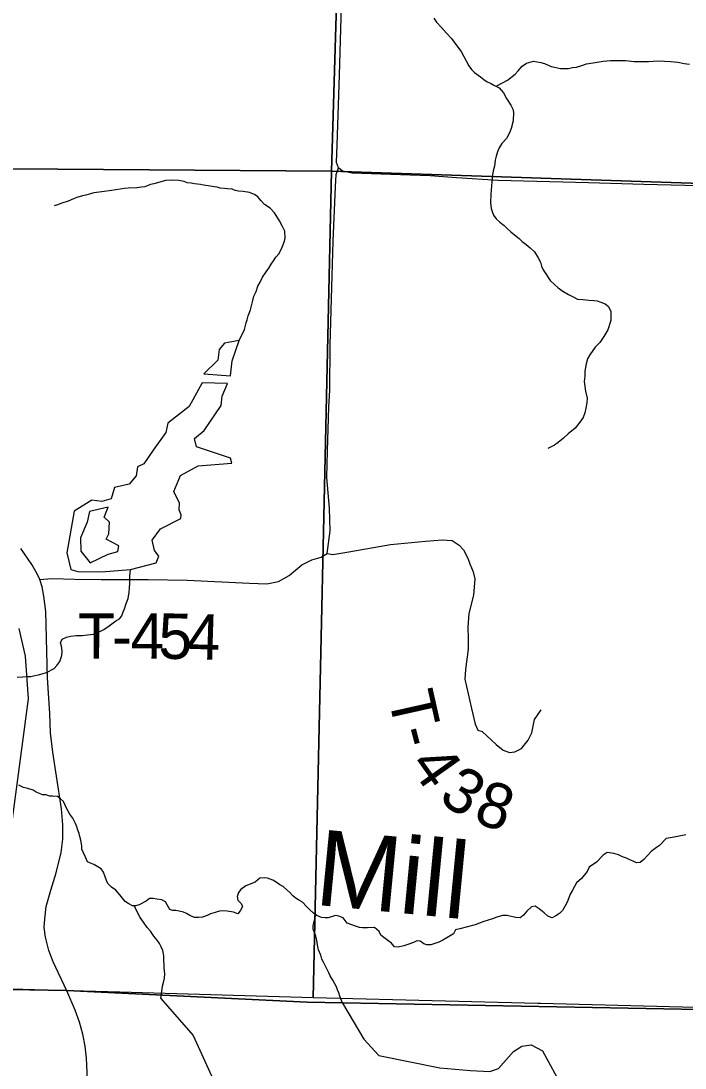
# Model space of a CAD drawing. Extents: x 0 to 34, y 0 to 22.
# Drawn here: x 5.636 to 6.467, y 16.238 to 17.548 of the extents above; entities that cross this region are included whole.
import ezdxf

# ---------------------------------------------------------------- set-up
doc = ezdxf.new("R2010")
doc.units = 0
for name, color, linetype in [('GM_X_Corporation', 7, 'Continuous'), ('GM_X_County_Road', 7, 'Continuous'), ('GM_X_Minor_Lake', 7, 'Continuous'), ('GM_X_Minor_River', 7, 'Continuous'), ('GM_X_Minor_River_Text', 7, 'Continuous'), ('GM_X_Rail_Line', 7, 'Continuous'), ('GM_X_State_Route', 7, 'Continuous'), ('GM_X_Township_Road', 7, 'Continuous'), ('GM_X_Township_Road_Text', 7, 'Continuous')]:
    doc.layers.add(name, color=color, linetype=linetype)

msp = doc.modelspace()

# ---------------------------------------------------------------- linework, layer by layer
at = {"layer": 'GM_X_Corporation'}
for points in [[(4.9914, 16.3477), (5.6931, 16.3352), (5.9938, 16.3204), (6.9309, 16.303), (7.0302, 16.2995), (7.0491, 16.2993), (8.0233, 16.275), (8.785, 16.2515), (8.9, 16.2485), (8.9, 20.9), (2.1, 20.9)], [(4.9914, 16.3477), (5.6931, 16.3352), (5.9938, 16.3204), (6.9309, 16.303), (7.0302, 16.2995), (7.0306, 16.367), (7.0337, 16.3927), (7.0334, 16.423), (7.0339, 16.4517), (7.0342, 16.5147), (7.0361, 16.5712), (7.0442, 17.0463), (7.0729, 18.3402), (7.0876, 19.4092), (7.1008, 19.81), (7.1249, 20.7061), (7.1302, 20.9), (2.2795, 20.9)], [(8.9, 14.5591), (8.9, 16.2485), (8.785, 16.2515), (8.0233, 16.275), (7.0491, 16.2993), (7.0302, 16.2995), (6.9309, 16.303), (5.9938, 16.3204), (5.6931, 16.3352), (4.9914, 16.3477), (4.4958, 16.358), (3.9899, 16.3631), (3.7537, 16.3728), (3.6165, 16.3686), (3.0057, 16.3809), (2.7707, 16.392), (2.3623, 16.41), (2.2605, 16.4147), (2.1155, 16.4201), (2.1, 15.9517)], [(8.9, 14.1), (8.9, 16.2485), (8.785, 16.2515), (8.0233, 16.275), (7.0491, 16.2993), (7.0302, 16.2995), (6.9309, 16.303), (5.9938, 16.3204), (5.6931, 16.3352), (4.9914, 16.3477)]]:
    msp.add_lwpolyline(points, dxfattribs=at)
for points in [[(5.0167, 18.3983), (6.0547, 18.3798), (6.0244, 17.3604), (4.9971, 17.3675)], [(7.0725, 18.3472), (7.0493, 17.3262), (6.0244, 17.3604), (6.0547, 18.3798)], [(4.9971, 17.3675), (6.0244, 17.3604), (6.0014, 16.3259), (5.7595, 16.3331), (5.486, 16.3408), (5.2494, 16.3478), (4.9974, 16.3535)], [(6.0244, 17.3604), (7.0493, 17.3262), (7.0242, 16.3016), (6.7708, 16.3075), (6.5283, 16.3127), (6.2859, 16.3188), (6.2825, 16.3189), (6.018, 16.3254), (6.0014, 16.3259)]]:
    msp.add_lwpolyline(points, close=True, dxfattribs=at)
at = {"layer": 'GM_X_County_Road'}
for points in [[(6.033, 17.3642), (6.0307, 17.371), (6.0314, 17.3933), (6.0345, 17.4804), (6.0385, 17.6249), (6.0421, 17.7526), (6.0425, 17.7762), (6.0418, 17.8051), (6.0431, 17.8132), (6.0462, 17.8213), (6.0524, 17.8366)], [(6.5006, 17.3416), (6.4153, 17.3437), (6.3459, 17.3454), (6.2327, 17.3485), (6.1808, 17.3518), (6.1479, 17.3543), (6.1226, 17.3553), (6.0502, 17.3578), (6.0383, 17.3601), (6.033, 17.3642)]]:
    msp.add_lwpolyline(points, dxfattribs=at)
at = {"layer": 'GM_X_Minor_Lake'}
for points in [[(5.909, 17.1483), (5.8904, 17.1452), (5.884, 17.1369), (5.8822, 17.1236), (5.8648, 17.1065), (5.8981, 17.1043)], [(5.8981, 17.1043), (5.9, 17.1229), (5.909, 17.1483)], [(5.8626, 17.0955), (5.8463, 17.0659), (5.8195, 17.045), (5.8173, 17.0332), (5.8014, 17.0112), (5.7897, 16.9941), (5.7818, 16.9903), (5.7799, 16.9789), (5.7712, 16.9686), (5.7527, 16.9644), (5.7489, 16.9504), (5.7372, 16.9469), (5.7247, 16.9488), (5.7024, 16.9347), (5.6934, 16.8827), (5.6984, 16.8619), (5.7071, 16.8592), (5.7367, 16.8589), (5.7731, 16.862)], [(5.7731, 16.862), (5.8052, 16.8704), (5.8082, 16.8784), (5.8029, 16.8856), (5.7999, 16.8985), (5.8104, 16.9129), (5.8358, 16.9255), (5.8361, 16.9301), (5.8338, 16.9365), (5.8342, 16.9448), (5.8273, 16.9596), (5.8356, 16.9794), (5.8576, 16.9915), (5.8996, 16.9947), (5.8981, 17.0011), (5.8556, 17.0154), (5.8529, 17.0257), (5.865, 17.0356), (5.8865, 17.0671), (5.8876, 17.0789), (5.8944, 17.0944), (5.8626, 17.0955)], [(5.7448, 16.9397), (5.7217, 16.9344), (5.7187, 16.9211), (5.7104, 16.9013), (5.7108, 16.885), (5.7226, 16.8703)], [(5.7226, 16.8703), (5.745, 16.8809), (5.7571, 16.8844), (5.7582, 16.8916), (5.7423, 16.8999), (5.746, 16.9063), (5.7467, 16.9211), (5.7399, 16.9272), (5.7448, 16.9397)]]:
    msp.add_lwpolyline(points, dxfattribs=at)
at = {"layer": 'GM_X_Minor_River'}
for points in [[(6.1526, 17.5516), (6.1556, 17.5467), (6.1621, 17.5398), (6.1682, 17.533), (6.1746, 17.5262), (6.1811, 17.5171), (6.1864, 17.5099), (6.1899, 17.5035), (6.196, 17.4921), (6.1994, 17.4872), (6.2032, 17.4838), (6.2108, 17.4781), (6.215, 17.4747), (6.2191, 17.4721), (6.2233, 17.4702), (6.2275, 17.4679), (6.2343, 17.4645), (6.2397, 17.4581), (6.2435, 17.4513), (6.2488, 17.4429), (6.2511, 17.4376), (6.2522, 17.4339), (6.2515, 17.4232), (6.2493, 17.4137), (6.247, 17.4081), (6.2432, 17.4012), (6.2376, 17.3948)], [(6.2302, 17.4666), (6.2445, 17.474), (6.254, 17.4816), (6.2581, 17.4858), (6.2627, 17.4915), (6.2683, 17.4953), (6.277, 17.498), (6.2861, 17.4961), (6.2907, 17.495), (6.299, 17.4912), (6.3032, 17.4901), (6.3108, 17.4886), (6.321, 17.4886), (6.326, 17.4898), (6.3309, 17.4901), (6.3377, 17.4924), (6.3434, 17.4943), (6.3517, 17.4959), (6.3642, 17.4978), (6.3733, 17.4986), (6.3922, 17.4986), (6.4032, 17.4975), (6.421, 17.4975), (6.4267, 17.4979), (6.4366, 17.4983), (6.4411, 17.498), (6.4483, 17.4972), (6.4578, 17.4965), (6.4654, 17.495), (6.4722, 17.4942)], [(6.2376, 17.3948), (6.2342, 17.3894), (6.2319, 17.3845), (6.2304, 17.3788), (6.2293, 17.3739), (6.2282, 17.3663), (6.2267, 17.3606), (6.2252, 17.3526), (6.2248, 17.3473), (6.2245, 17.3413), (6.2237, 17.3314), (6.2234, 17.3204), (6.2242, 17.3136), (6.2253, 17.3098), (6.2272, 17.3052), (6.2303, 17.3007), (6.2348, 17.2962), (6.2402, 17.2924), (6.2443, 17.2886), (6.2489, 17.2844), (6.2534, 17.2806), (6.2591, 17.2761), (6.2629, 17.2723), (6.2679, 17.2685), (6.2728, 17.2644), (6.2785, 17.2591), (6.2831, 17.2519), (6.2858, 17.2462), (6.2873, 17.2413), (6.2892, 17.2367), (6.2915, 17.2329), (6.298, 17.2235), (6.3033, 17.2186), (6.3078, 17.2144), (6.3139, 17.2102), (6.3207, 17.2061), (6.3268, 17.2031), (6.3321, 17.2), (6.339, 17.1997), (6.3465, 17.1989), (6.3526, 17.1982), (6.3568, 17.1978), (6.3613, 17.1963), (6.3666, 17.1944), (6.3708, 17.191), (6.3739, 17.1846), (6.3739, 17.1732), (6.3701, 17.1618), (6.3649, 17.1534), (6.36, 17.1458), (6.3543, 17.1401), (6.3475, 17.1303), (6.3445, 17.1253), (6.343, 17.1193), (6.3415, 17.1098), (6.3411, 17.1037), (6.3404, 17.0969), (6.3423, 17.0851), (6.3442, 17.0764), (6.3439, 17.0703), (6.3424, 17.0635), (6.3413, 17.0578), (6.3394, 17.0521), (6.3352, 17.046), (6.3292, 17.0388), (6.3205, 17.0316), (6.3145, 17.0263), (6.308, 17.0206), (6.3035, 17.0175), (6.2952, 17.0133)], [(5.909, 17.1483), (5.9154, 17.162), (5.9177, 17.1703), (5.9188, 17.1741), (5.9203, 17.1791), (5.9229, 17.1867), (5.9248, 17.1935), (5.9259, 17.1984), (5.9274, 17.2037), (5.93, 17.2098), (5.9323, 17.2163), (5.9353, 17.2212), (5.938, 17.2276), (5.9425, 17.2341), (5.9459, 17.2387), (5.9489, 17.244), (5.9519, 17.2482), (5.9549, 17.2527), (5.9591, 17.2573), (5.9628, 17.2652), (5.9655, 17.2725), (5.9662, 17.277), (5.9658, 17.285), (5.9628, 17.2918), (5.9593, 17.2982), (5.9559, 17.3035), (5.9529, 17.3081), (5.9475, 17.3138), (5.9407, 17.3187), (5.9365, 17.3232), (5.9323, 17.3281), (5.9282, 17.3308), (5.9217, 17.3334), (5.9138, 17.3349), (5.9081, 17.3353), (5.9039, 17.336), (5.9001, 17.3375), (5.8944, 17.3379), (5.8903, 17.3387), (5.8849, 17.339), (5.8812, 17.3402), (5.8774, 17.3405), (5.8702, 17.342), (5.8641, 17.3428), (5.8603, 17.3435), (5.8531, 17.3443), (5.8489, 17.345), (5.844, 17.3458), (5.8402, 17.3473), (5.8334, 17.3484), (5.8239, 17.3488), (5.8167, 17.3484), (5.8125, 17.3472), (5.8019, 17.3442), (5.7978, 17.3434), (5.791, 17.3407), (5.7868, 17.3403), (5.7807, 17.3392), (5.7698, 17.3388), (5.7652, 17.3384), (5.7546, 17.3369), (5.7493, 17.3361), (5.7372, 17.3342), (5.7269, 17.333), (5.7228, 17.3319), (5.7171, 17.33), (5.7129, 17.3292), (5.7057, 17.3273), (5.7016, 17.3257), (5.6951, 17.3227), (5.6868, 17.32), (5.6815, 17.3181), (5.6774, 17.317)], [(5.6313, 16.727), (5.6378, 16.7274), (5.6431, 16.7278), (5.6484, 16.7278), (5.6533, 16.7294), (5.6579, 16.7301), (5.6677, 16.7328), (5.6775, 16.7381), (5.6806, 16.7419), (5.6847, 16.7469), (5.687, 16.7541), (5.6873, 16.7598), (5.6866, 16.7659), (5.6854, 16.77), (5.6873, 16.7746), (5.693, 16.7773), (5.6979, 16.7784), (5.7051, 16.7792), (5.7123, 16.7792), (5.7191, 16.78), (5.7267, 16.7811), (5.7327, 16.7834), (5.7395, 16.7868), (5.7464, 16.7914), (5.7547, 16.7975), (5.7592, 16.8002), (5.7619, 16.804), (5.7637, 16.8089), (5.7652, 16.8127), (5.7675, 16.8195), (5.7698, 16.8256), (5.7712, 16.8336), (5.7716, 16.8385), (5.772, 16.8446), (5.7719, 16.8533), (5.7731, 16.862), (5.7731, 16.862)], [(5.7321, 16.4898), (5.7271, 16.4928), (5.723, 16.4943), (5.7192, 16.4962), (5.7165, 16.5019), (5.7135, 16.5083), (5.7119, 16.5121), (5.7119, 16.5163), (5.7108, 16.5231), (5.7096, 16.5277), (5.7085, 16.5314), (5.7069, 16.5356), (5.7058, 16.5398), (5.7039, 16.5443), (5.7008, 16.5508), (5.697, 16.5557), (5.6951, 16.5595), (5.6928, 16.5633), (5.6913, 16.5671), (5.689, 16.5716), (5.6852, 16.575), (5.6814, 16.5777), (5.6754, 16.5784), (5.6716, 16.5784), (5.6674, 16.5799), (5.6628, 16.5799), (5.6591, 16.5818), (5.6549, 16.5833), (5.6511, 16.5856), (5.6443, 16.5878), (5.6389, 16.589), (5.6333, 16.592)], [(6.4675, 16.53), (6.4614, 16.5285), (6.4531, 16.5269), (6.4432, 16.5254), (6.4349, 16.5166), (6.4308, 16.514), (6.4243, 16.509), (6.4153, 16.4991), (6.4107, 16.4953), (6.4058, 16.495), (6.4016, 16.4968), (6.3978, 16.4987), (6.3933, 16.5006), (6.3884, 16.5025), (6.3834, 16.5048), (6.3774, 16.5067), (6.3694, 16.5078), (6.3641, 16.5044), (6.3558, 16.4956), (6.3467, 16.4895), (6.3441, 16.4842), (6.3373, 16.4751), (6.3309, 16.4698), (6.3282, 16.4652), (6.3256, 16.4599), (6.3229, 16.4557), (6.3214, 16.4511), (6.3192, 16.4458), (6.3169, 16.4409), (6.3135, 16.4352), (6.3097, 16.4314), (6.3052, 16.4284), (6.3003, 16.4261), (6.295, 16.428), (6.2904, 16.4325), (6.284, 16.4374), (6.279, 16.4408), (6.2745, 16.4397), (6.2688, 16.4343), (6.2647, 16.4294), (6.2605, 16.426), (6.2548, 16.4263), (6.2491, 16.4279), (6.2442, 16.429), (6.2381, 16.429), (6.2313, 16.4271), (6.2256, 16.4248), (6.2203, 16.4232), (6.215, 16.4213), (6.2041, 16.4175)], [(6.2041, 16.4175), (6.1851, 16.4122), (6.1794, 16.411), (6.1768, 16.4061), (6.1685, 16.4011), (6.1636, 16.3981), (6.1586, 16.3958), (6.1537, 16.3939), (6.1488, 16.3924), (6.1435, 16.3924), (6.1397, 16.3935), (6.1351, 16.3969), (6.131, 16.3973), (6.1268, 16.3954), (6.1211, 16.3931), (6.1147, 16.3912), (6.1079, 16.3892), (6.1033, 16.39), (6.0995, 16.3942), (6.095, 16.3976), (6.09, 16.4013), (6.0859, 16.4044), (6.084, 16.4089), (6.0783, 16.4138), (6.0695, 16.4134), (6.0631, 16.4134), (6.0593, 16.4138), (6.0544, 16.4157), (6.0487, 16.4176), (6.0438, 16.4195), (6.0388, 16.4259), (6.0335, 16.4282), (6.0293, 16.4289), (6.0202, 16.4262), (6.0165, 16.4262), (6.0119, 16.4266), (6.0062, 16.4289), (6.002, 16.4319), (5.9967, 16.4364), (5.9929, 16.4402), (5.988, 16.4455), (5.9842, 16.4478), (5.98, 16.4504), (5.9758, 16.4535), (5.9724, 16.4576), (5.9686, 16.461), (5.9637, 16.4652), (5.9599, 16.4675), (5.9553, 16.4709), (5.9508, 16.4731), (5.9443, 16.4758), (5.9401, 16.4762), (5.9348, 16.4758), (5.9288, 16.4708), (5.9174, 16.4662), (5.911, 16.4617), (5.908, 16.4579), (5.9065, 16.4529), (5.9073, 16.448), (5.9114, 16.4442), (5.913, 16.4404), (5.9103, 16.4347), (5.9073, 16.4309), (5.9016, 16.4332), (5.894, 16.4343), (5.888, 16.4347), (5.8842, 16.4343), (5.8789, 16.4328), (5.8728, 16.4309), (5.8687, 16.429), (5.863, 16.4271), (5.8581, 16.4263), (5.8528, 16.4263), (5.8471, 16.4289), (5.8429, 16.4316), (5.8391, 16.4331), (5.8338, 16.4346), (5.8296, 16.4353), (5.8258, 16.4353), (5.822, 16.4365), (5.8186, 16.4425), (5.8167, 16.4463), (5.8121, 16.4486), (5.8057, 16.4493), (5.8012, 16.4501), (5.7966, 16.4501), (5.7924, 16.447), (5.7837, 16.4424), (5.7792, 16.4409), (5.7754, 16.4413), (5.7709, 16.4436), (5.7663, 16.4466), (5.7595, 16.4549), (5.7545, 16.4606), (5.7492, 16.4644), (5.7446, 16.4689), (5.7427, 16.4727), (5.7412, 16.4773), (5.7393, 16.4833), (5.7362, 16.4875), (5.7321, 16.4898)], [(5.8108, 16.3252), (5.8128, 16.3404), (5.8143, 16.345), (5.8155, 16.3507), (5.8158, 16.356), (5.815, 16.3636), (5.815, 16.3678), (5.8146, 16.3723), (5.8146, 16.3784), (5.8135, 16.3852), (5.8112, 16.3898), (5.8093, 16.3939), (5.8062, 16.3981), (5.802, 16.403), (5.7979, 16.4095), (5.7937, 16.414), (5.7891, 16.4208), (5.7849, 16.4265), (5.7826, 16.4311), (5.78, 16.4367), (5.7773, 16.4411)], [(6.038, 16.3192), (6.0346, 16.328), (6.0334, 16.3322), (6.0319, 16.336), (6.0307, 16.3398), (6.0284, 16.3435), (6.0262, 16.3481), (6.0227, 16.3534), (6.0212, 16.3572), (6.0174, 16.3648), (6.0143, 16.3705), (6.0121, 16.3742), (6.0109, 16.3792), (6.0082, 16.386), (6.0067, 16.3921), (6.0059, 16.3981), (6.0048, 16.4031), (6.0029, 16.4076), (6.0013, 16.4118), (6.0013, 16.4167), (6.0046, 16.43)], [(5.8108, 16.3252), (5.8511, 16.2789), (5.8741, 16.2285), (5.8768, 16.2035), (5.8755, 16.1629), (5.8828, 16.1356), (5.8882, 16.1136), (5.8984, 16.1015), (5.9201, 16.0883), (5.9456, 16.0451), (5.9551, 16.0349), (5.9984, 16.0093), (6.0201, 15.987), (6.0296, 15.9764), (6.0398, 15.9703), (6.0599, 15.9662), (6.0676, 15.9499)], [(6.038, 16.3192), (6.065, 16.2743), (6.0837, 16.2539), (6.1598, 16.2386), (6.1981, 16.2353), (6.2223, 16.2339), (6.2333, 16.2377), (6.2521, 16.259), (6.2623, 16.2655), (6.274, 16.267), (6.2884, 16.2599), (6.3136, 16.2129), (6.3372, 16.1857), (6.352, 16.177), (6.4191, 16.1609), (6.452, 16.1648), (6.4641, 16.1626), (6.5013, 16.146), (6.5293, 16.1435), (6.5407, 16.139), (6.5506, 16.136), (6.5604, 16.1341)]]:
    msp.add_lwpolyline(points, dxfattribs=at)
at = {"layer": 'GM_X_Rail_Line'}
msp.add_lwpolyline([(5.6126, 16.4552), (5.6451, 16.7001), (5.6414, 16.7533), (5.6337, 16.7879)], dxfattribs=at)
at = {"layer": 'GM_X_State_Route'}
for points in [[(5.6933, 16.3346), (5.6761, 16.3709), (5.6706, 16.3852), (5.6665, 16.4018), (5.6651, 16.4142), (5.6656, 16.4247), (5.6675, 16.4401), (5.6731, 16.4605), (5.6799, 16.4824), (5.6861, 16.5078), (5.6883, 16.5246), (5.6883, 16.5425), (5.6866, 16.5624), (5.6802, 16.6035), (5.6759, 16.6335), (5.673, 16.6576), (5.6718, 16.6816), (5.6692, 16.7263), (5.6668, 16.8094), (5.6644, 16.8285), (5.6622, 16.84), (5.6596, 16.8493), (5.656, 16.8563), (5.6495, 16.8683), (5.6356, 16.8881)], [(5.719, 16.1697), (5.7194, 16.1783), (5.7192, 16.2219), (5.7187, 16.233), (5.7177, 16.2507), (5.716, 16.2654), (5.7131, 16.2807), (5.709, 16.2957), (5.7037, 16.3104), (5.6933, 16.3346)]]:
    msp.add_lwpolyline(points, dxfattribs=at)
at = {"layer": 'GM_X_Township_Road'}
for points in [[(6.019, 16.8818), (6.0228, 16.9102), (6.0218, 16.9388), (6.0185, 16.9768), (6.0193, 17.0102), (6.0211, 17.0649), (6.0224, 17.0861), (6.0228, 17.1431), (6.0264, 17.2728), (6.0292, 17.3404), (6.0302, 17.3561), (6.033, 17.3642)], [(6.019, 16.8818), (6.0259, 16.8805), (6.0461, 16.8841), (6.0983, 16.8932), (6.1421, 16.8975), (6.1629, 16.899), (6.1753, 16.898), (6.1841, 16.8922), (6.1897, 16.8866), (6.1948, 16.8762), (6.1975, 16.8691), (6.2018, 16.859), (6.2036, 16.8502), (6.2021, 16.8296), (6.1963, 16.8069), (6.1948, 16.7899), (6.1953, 16.7755), (6.1953, 16.762), (6.192, 16.7367), (6.1912, 16.7248), (6.1996, 16.6881), (6.2041, 16.6683), (6.2074, 16.6607), (6.213, 16.6592), (6.2305, 16.643), (6.2393, 16.6357), (6.2469, 16.6331), (6.2538, 16.6337), (6.2621, 16.638), (6.2705, 16.6483), (6.275, 16.6575), (6.2783, 16.6742), (6.2867, 16.6863)], [(5.6596, 16.8493), (5.6744, 16.8505), (5.7031, 16.8498), (5.7362, 16.8493), (5.795, 16.8493), (5.8436, 16.8486), (5.9218, 16.8448), (5.9436, 16.8441), (5.958, 16.8469), (5.9714, 16.8542), (5.9871, 16.8677), (5.9998, 16.874), (6.0114, 16.8775), (6.019, 16.8818)]]:
    msp.add_lwpolyline(points, dxfattribs=at)

# ---------------------------------------------------------------- texts
at = {"layer": 'GM_X_Minor_River_Text'}
msp.add_text('Mill', height=0.0947, rotation=354.4644, dxfattribs=at).set_placement((6.002, 16.4426))
at = {"layer": 'GM_X_Township_Road_Text'}
for s, rotation, p in [('T', 359.9957, (5.707, 16.7503)), ('4', 359.8335, (5.7728, 16.7503)), ('5', 359.4692, (5.8077, 16.7502)), ('4', 358.2304, (5.8424, 16.7499)), ('-', 359.961, (5.7495, 16.7503)), ('T', 282.6329, (6.0949, 16.7035)), ('-', 284.7269, (6.1048, 16.6598)), ('4', 305.4012, (6.1201, 16.6171)), ('3', 326.3065, (6.1565, 16.5729)), ('8', 341.3364, (6.2002, 16.5464))]:
    msp.add_text(s, height=0.0568, rotation=rotation, dxfattribs=at).set_placement(p)

doc.saveas('drawing.dxf')
